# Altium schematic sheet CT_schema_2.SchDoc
size 283 x 147 mm
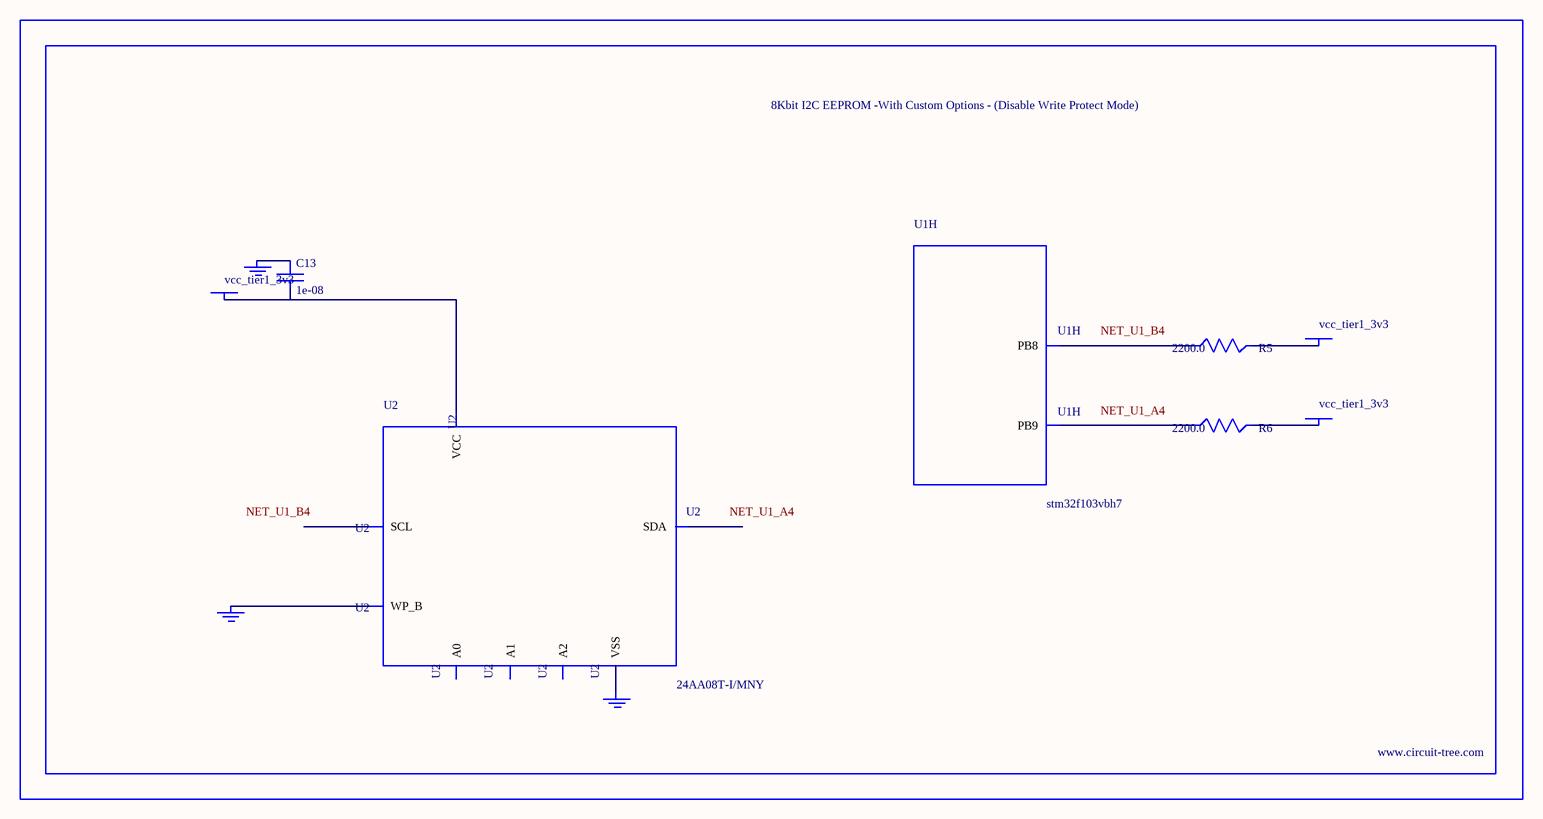
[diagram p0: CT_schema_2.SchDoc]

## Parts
BORDER1  (no value)
C13  1e-08  [C0402]
GND_INSTANCE_1_0  (no value)
GND_INSTANCE_1_1  (no value)
GND_INSTANCE_1_2  (no value)
POWER_INSTANCE_1_0  vcc_tier1_3v3
POWER_INSTANCE_1_1  vcc_tier1_3v3
POWER_INSTANCE_1_2  vcc_tier1_3v3
R5  2200.0  [R0603]
R6  2200.0  [R0603]
U1  stm32f103vbh7  [LFBGA100]  (part H of 10)
U2  24AA08T-I/MNY  [TDFN-8/6MM]

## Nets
NetC13_1: C13.1 GND_INSTANCE_1_1.0(GND)
NetC13_2: C13.2 POWER_INSTANCE_1_0.0(PWR) U2.8(VCC)
NetGND_INSTANCE_1_0_0: GND_INSTANCE_1_0.0(GND) U2.7(WP_B)
NetGND_INSTANCE_1_2_0: GND_INSTANCE_1_2.0(GND) U2.4(VSS)
NetPOWER_INSTANCE_1_1_0: POWER_INSTANCE_1_1.0(PWR) R5.2
NetPOWER_INSTANCE_1_2_0: POWER_INSTANCE_1_2.0(PWR) R6.2
NetR5_1: R5.1 U1.B4(PB8)
NetR6_1: R6.1 U1.A4(PB9)

Not connected (* = marked no-connect by the designer): U2 1(A0) 2(A1) 3(A2) 5(SDA) 6(SCL)

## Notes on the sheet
- Labels drawn without touching a wire or pin: NET_U1_A4, NET_U1_B4

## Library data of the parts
BORDER1 = BORDER_PAGE1
C13 = C0402C103K3RAC
GND_INSTANCE_1_0-GND_INSTANCE_1_2 = GND
POWER_INSTANCE_1_0-POWER_INSTANCE_1_2 = PWR
R5 R6 = RC0603JR-072K2L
